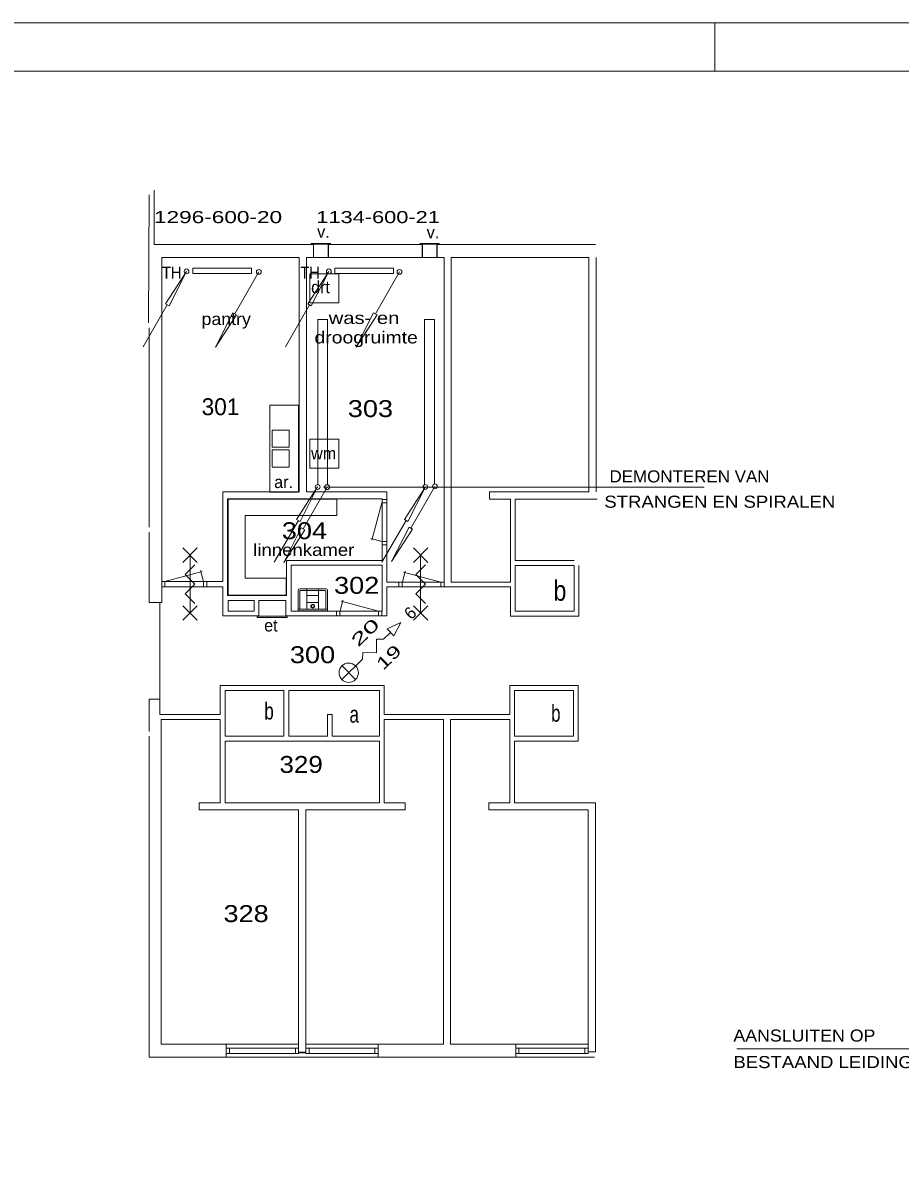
# Model space of a CAD drawing. Extents: x 295824 to 414724, y 24924 to 109024.
# Drawn here: x 358386 to 376562, y 85348 to 109024 of the extents above; entities that cross this region are included whole.
import ezdxf
from ezdxf.enums import TextEntityAlignment as Align

# ---------------------------------------------------------------- set-up
doc = ezdxf.new("R2010")
doc.units = 0
doc.header["$LTSCALE"] = 100
for name, color, linetype, lineweight in [('1', 7, 'Continuous', 13), ('16', 7, 'Continuous', 13), ('61', 7, 'Continuous', 13)]:
    doc.layers.add(name, color=color, linetype=linetype, lineweight=lineweight)

msp = doc.modelspace()

# ---------------------------------------------------------------- linework, layer by layer
at = {"layer": '1'}
msp.add_line((372723.6, 108023.8), (372723.6, 109023.8), dxfattribs=at)
for points in [[(414723.6, 109023.8), (304995.6, 109023.8), (295823.6, 109023.8)], [(304995.6, 25923.8), (413723.6, 25923.8), (413723.6, 108023.8), (304995.6, 108023.8)]]:
    msp.add_lwpolyline(points, dxfattribs=at)
at = {"layer": '16'}
for p, q in [((363274.9, 103866.3), (362774.9, 103000.3)), ((366189.7, 103866.3), (365689.7, 103000.3)), ((360877.9, 102318.1), (361377.9, 103184.1)), ((363826.1, 102318.1), (364326.1, 103184.1)), ((364690.9, 99408.9), (364190.9, 98542.9)), ((364615, 99410.3), (372499.2, 99410.3)), ((366922.9, 99425.5), (366422.9, 98559.5)), ((363593.8, 97854.5), (364093.8, 98720.5)), ((365825.8, 97854.5), (366325.8, 98720.5)), ((383727.1, 87777.8), (373178.7, 87777.8))]:
    msp.add_line(p, q, dxfattribs=at)
for points in [[(361905.5, 103836.3), (363122.2, 103836.3), (363122.2, 103943.5), (361905.5, 103943.5)], [(364850.9, 103836.3), (366067.6, 103836.3), (366067.6, 103943.5), (364850.9, 103943.5)], [(361777.9, 103877.1), (361413.9, 103163.1), (361341.9, 103205.1)], [(364726.1, 103877.1), (364362.1, 103163.1), (364290.1, 103205.1)], [(362374.9, 102307.3), (362738.9, 103021.3), (362810.9, 102979.3)], [(365289.7, 102307.3), (365653.7, 103021.3), (365725.7, 102979.3)], [(364493.8, 99413.5), (364129.8, 98699.5), (364057.8, 98741.5)], [(366725.8, 99413.5), (366361.8, 98699.5), (366289.8, 98741.5)], [(363790.9, 97849.9), (364154.9, 98563.9), (364226.9, 98521.9)], [(366022.9, 97866.5), (366386.9, 98580.5), (366458.9, 98538.5)]]:
    msp.add_lwpolyline(points, close=True, dxfattribs=at)
for points in [[(364494.9, 99450.9), (364494.9, 102882.9), (364697.3, 102882.9), (364697.3, 99462.8)], [(366710, 99450.9), (366710, 102882.9), (366912.5, 102882.9), (366912.5, 99462.8)]]:
    msp.add_lwpolyline(points, dxfattribs=at)
for centre in [(361777.9, 103876.8), (363274.9, 103866.6), (364726.1, 103876.8), (366189.7, 103866.6), (364493.8, 99413.2), (364690.9, 99409.2), (366725.7, 99413.2), (366922.9, 99425.8)]:
    msp.add_circle(centre, 50, dxfattribs=at)
at = {"layer": '61'}
for p, q in [((360992, 102809.9), (361005, 105459.9)), ((361105, 105559.9), (361105, 104434.8)), ((361105, 104434.8), (364405.1, 104434.8)), ((364758.7, 104455), (364360.4, 104455)), ((364360.4, 104455), (364360.4, 104439.9)), ((364758.7, 104439.9), (364360.4, 104439.9)), ((364405.1, 104434.8), (364405.1, 104164.8)), ((364410.7, 104439.9), (364410.7, 104165.5)), ((364709.4, 104439.9), (364709.4, 104165.5)), ((364715.8, 104433.5), (364715.8, 104165)), ((364715.8, 104433.5), (366658.8, 104433.5)), ((364758.7, 104455), (364758.7, 104439.9)), ((367012.4, 104455), (366614.1, 104455)), ((366614.1, 104455), (366614.1, 104439.9)), ((367012.4, 104439.9), (366614.1, 104439.9)), ((366658.8, 104433.5), (366658.8, 104165)), ((366664.4, 104439.9), (366664.4, 104165.5)), ((366963.1, 104439.9), (366963.1, 104165.5)), ((366969.5, 104433.4), (370247.5, 104433.4)), ((366969.5, 104433.4), (366969.5, 104163.4)), ((367012.4, 104455), (367012.4, 104439.9)), ((361262, 97018.8), (361262, 104163.4)), ((364262, 104164.8), (364405.1, 104164.8)), ((364262, 99313.4), (364262, 104163.5)), ((367112, 104163.5), (364262, 104163.5)), ((364709.4, 104165.5), (364410.7, 104165.5)), ((364715.8, 104165), (364861.6, 104165)), ((366512.1, 104165), (366658.8, 104165)), ((366963.1, 104165.5), (366664.4, 104165.5)), ((366969.5, 104163.4), (367112, 104163.4)), ((367112, 97344.7), (367112, 104163.5)), ((370262, 104163.4), (370262, 99313.4)), ((361005, 102709.9), (361005, 98580.1)), ((363552.5, 100587.8), (363902.5, 100587.8)), ((363903.3, 100586.2), (363903.3, 100236.2)), ((363902.5, 100233.7), (363552.5, 100233.7)), ((363552.5, 100179.6), (363902.5, 100179.6)), ((363903.3, 100178), (363903.3, 99828)), ((363902.5, 99825.5), (363552.5, 99825.5)), ((362527.3, 99313.4), (362527.3, 97457.3)), ((364262, 99313.4), (365927.3, 99313.4)), ((362627.3, 97163.1), (362627.3, 99168.1)), ((365825.3, 99083.9), (365618.3, 98311.1)), ((365926.8, 99150.1), (365826, 99150.1)), ((365924.8, 99083.1), (365827.3, 99083.1)), ((365925.2, 99150.1), (365828.5, 99150.1)), ((368587, 97888.4), (368587, 99162.1)), ((370283.5, 99162.1), (368587, 99162.1)), ((365824.7, 98285.5), (365597.9, 98346.2)), ((365924.6, 98283.1), (365826, 98283.1)), ((362000.3, 98152), (361700.3, 97852)), ((361700.3, 98152), (362000.3, 97852)), ((365924.8, 98216.1), (365826, 98216.1)), ((366777.5, 98152), (366477.5, 97852)), ((366477.5, 98152), (366777.5, 97852)), ((361850.3, 96802), (361850.3, 98002)), ((366627.5, 96802), (366627.5, 98002)), ((368587, 97888.4), (369807, 97888.4)), ((369907, 96738.4), (369907, 97788.4)), ((361328.9, 97457.9), (362101.7, 97665)), ((362127.4, 97458.6), (362066.6, 97685.4)), ((366248, 97444.2), (366308.8, 97671.1)), ((367046.5, 97443.6), (366273.7, 97650.6)), ((361329.7, 97343.3), (361329.7, 97457.3)), ((362129.7, 97343.3), (362129.7, 97457.3)), ((362196.7, 97343.3), (362196.7, 97457.3)), ((362527.3, 96743.1), (362527.3, 97343.3)), ((365927.3, 97344.7), (367115.7, 97344.7)), ((365927.3, 97343.1), (365927.3, 96743.1)), ((366178.7, 97344.1), (366178.7, 97443)), ((366245.7, 97344.3), (366245.7, 97443)), ((367045.7, 97344.1), (367045.7, 97443)), ((367112, 97344.7), (368487, 97344.7)), ((367112.7, 97344.7), (367112.7, 97443.1)), ((368487, 96738.4), (368487, 97344.7)), ((363847.3, 97163.1), (362627.3, 97163.1)), ((364087.5, 97269.8), (364087.5, 96854.8)), ((364662.5, 97304.8), (364122.5, 97304.8)), ((364122.5, 96894.8), (364122.5, 97254.8)), ((364137.5, 97269.8), (364647.5, 97269.8)), ((364272.5, 96879.8), (364272.5, 97304.8)), ((364512.5, 97163.1), (364272.5, 97163.1)), ((364512.5, 96879.8), (364512.5, 97304.8)), ((364662.5, 97254.8), (364662.5, 96894.8)), ((364697.5, 96854.8), (364697.5, 97269.8)), ((364956.7, 96843.2), (365017.5, 97070.1)), ((361225, 97018.8), (361225, 94699.2)), ((362000.3, 96952), (361700.3, 96652)), ((361700.3, 96952), (362000.3, 96652)), ((362637.3, 96843.1), (362637.3, 97063.1)), ((363177.3, 97063.1), (362637.3, 97063.1)), ((363177.3, 96843.1), (362637.3, 96843.1)), ((363177.3, 96843.1), (363177.3, 97063.1)), ((363277.3, 96743.1), (363277.3, 97063.1)), ((363837.3, 97063.1), (363277.3, 97063.1)), ((363837.3, 96743.1), (363837.3, 97063.1)), ((364687.5, 96879.8), (364097.5, 96879.8)), ((364097.5, 96844.8), (364687.5, 96844.8)), ((364512.5, 97021.5), (364272.5, 97021.5)), ((364887.4, 96743.1), (364887.4, 96842)), ((364954.4, 96743.3), (364954.4, 96842)), ((365755.2, 96842.6), (364982.4, 97049.6)), ((365754.4, 96743.1), (365754.4, 96842)), ((365821.4, 96743.1), (365821.4, 96842)), ((366777.5, 96952), (366477.5, 96652)), ((366477.5, 96952), (366777.5, 96652)), ((363277.3, 96743.1), (362527.3, 96743.1)), ((363243.1, 96736), (363861.5, 96736)), ((363243.1, 96708.2), (363243.1, 96736)), ((365927.3, 96743.1), (363837.3, 96743.1)), ((369907, 96738.4), (368487, 96738.4)), ((364998.1, 95710.2), (365276, 95422.5)), ((362474.3, 95299.2), (362474.3, 94699.2)), ((365874.3, 95299.2), (362474.3, 95299.2)), ((365874.3, 94699.2), (365874.3, 95299.2)), ((369894.3, 95299.2), (369894.3, 94149.2)), ((362474.3, 94699.2), (361225, 94699.2)), ((361005, 94250.3), (361005, 87604.2)), ((368574.3, 94149.2), (368574.3, 92874.6)), ((368574.3, 94149.2), (369894.3, 94149.2)), ((370249.3, 92874.6), (368574.3, 92874.6)), ((370249.3, 87713.6), (370249.3, 92874.6)), ((361249.3, 87874.2), (364099.3, 87874.2)), ((362600.6, 87599.6), (362600.6, 87869.6)), ((367099.3, 87874.2), (364249.3, 87874.2)), ((365748.6, 87599.6), (365748.6, 87869.7)), ((367249.3, 87874.2), (370099.3, 87874.2)), ((368597.5, 87602.1), (368597.5, 87872.1)), ((361005, 87604.2), (370229.2, 87604.2)), ((362667.3, 87677.8), (362667.3, 87791.7)), ((364032.3, 87677.2), (364032.3, 87791.2)), ((364099.3, 87707.2), (364249.3, 87707.2)), ((364099.3, 87692.2), (364249.3, 87692.2)), ((364315.8, 87678.2), (364315.8, 87792.2)), ((365680.2, 87677.9), (365680.2, 87791.5)), ((368664.2, 87677.8), (368664.2, 87791.7)), ((370029.2, 87677.2), (370029.2, 87791.2)), ((370097.8, 87713.6), (370249.3, 87713.6))]:
    msp.add_line(p, q, dxfattribs=at)
for points in [[(361262, 104163.4), (364112, 104163.4), (364112, 99313.4), (362527.3, 99313.4)], [(363504.2, 99307.9), (364098.9, 99307.9), (364098.9, 101107.9)], [(363504.2, 99307.9), (363504.2, 101107.9), (364098.9, 101107.9)], [(363553.3, 100236.2), (363553.3, 100586.2), (363552.5, 100587.8)], [(363553.3, 99828), (363553.3, 100178), (363552.5, 100179.6)], [(365927.3, 99313.4), (365927.3, 97443.1), (367112.7, 97443.1)], [(362627.3, 99168.1), (365827.3, 99168.1), (365827.3, 97893.1), (363847.3, 97893.1), (363847.3, 97163.1)], [(361005, 98480.1), (361005, 97018.8), (361262, 97018.8)], [(361950.3, 97002), (361750.3, 97202), (361950.3, 97402), (361750.3, 97602), (361950.3, 97802)], [(366727.5, 97002), (366527.5, 97202), (366727.5, 97402), (366527.5, 97602), (366727.5, 97802)], [(361262.7, 97343.3), (361262.7, 97457.3), (362527.3, 97457.3)], [(362527.3, 97343.3), (361262.7, 97343.3), (361262.7, 97457.3)], [(363243.1, 96708.2), (363861.5, 96708.2), (363861.5, 96736)], [(364993.2, 95427.4), (365424.8, 95844.2), (365427.3, 95985.6), (365710.1, 95980.7), (365715, 96263.5), (365856.4, 96261), (366000.2, 96399.9)], [(369894.3, 95299.2), (368474.3, 95299.2), (368474.3, 94699.2)], [(361225, 95018.8), (361005, 95018.8), (361005, 94350.3)], [(364099.3, 87692.2), (364099.3, 92724.2), (362039.3, 92724.2), (362039.3, 92874.2), (362474.3, 92874.2), (362474.3, 94599.2), (361249.3, 94599.2), (361249.3, 87874.2)], [(364249.3, 87692.2), (364249.3, 92724.2), (366309.3, 92724.2), (366309.3, 92874.2), (365874.3, 92874.2), (365874.3, 94599.2), (367099.3, 94599.2), (367099.3, 87874.2)], [(365874.3, 94699.2), (368474.3, 94699.2), (367249.3, 94699.2)], [(370099.3, 87713.6), (370099.3, 92724.2), (368039.3, 92724.2), (368039.3, 92874.2), (368474.3, 92874.2), (368474.3, 94599.2), (367249.3, 94599.2), (367249.3, 87874.2)]]:
    msp.add_lwpolyline(points, dxfattribs=at)
for points in [[(367262, 104163.4), (370112, 104163.4), (370112, 99313.4), (368052, 99313.4), (368052, 99163.4), (368487, 99163.4), (368487, 97438.4), (367262, 97438.4)], [(364333.5, 103228.2), (364333.5, 103828.2), (364933.5, 103828.2), (364933.5, 103228.2)], [(364333.5, 99805.5), (364333.5, 100405.5), (364933.5, 100405.5), (364933.5, 99805.5)], [(362640, 97169.8), (362640, 99163.4), (364890.7, 99163.4), (364890.7, 98823.2), (362990, 98823.2), (362990, 97520.9), (363840.2, 97520.9), (363840.2, 97169.8)], [(363947.3, 97793.1), (365827.3, 97793.1), (365827.3, 96843.1), (363947.3, 96843.1)], [(368587, 97788.4), (369807, 97788.4), (369807, 96838.4), (368587, 96838.4)], [(366069.7, 96328), (365930.8, 96471.9), (366216, 96608.3)], [(362574.3, 94249.2), (363794.3, 94249.2), (363794.3, 95199.2), (362574.3, 95199.2)], [(363894.3, 94249.2), (364694.3, 94249.2), (364694.3, 94699.2), (364794.3, 94699.2), (364794.3, 94249.2), (365774.3, 94249.2), (365774.3, 95199.2), (363894.3, 95199.2)], [(368574.3, 94249.2), (369794.3, 94249.2), (369794.3, 95199.2), (368574.3, 95199.2)], [(362574.3, 92874.2), (365774.3, 92874.2), (365774.3, 94149.2), (362574.3, 94149.2)], [(362600.5, 87677.7), (362600.5, 87791.7), (364099.2, 87791.7), (364099.2, 87677.7)], [(364249.5, 87677.9), (364249.5, 87791.9), (365748.9, 87791.9), (365748.9, 87677.9)], [(368597.4, 87677.7), (368597.4, 87791.7), (370096, 87791.7), (370096, 87677.7)]]:
    msp.add_lwpolyline(points, close=True, dxfattribs=at)
for centre, radius in [((364392.5, 96944.8), 40), ((364392.5, 96944.8), 30), ((365137, 95566.3), 200)]:
    msp.add_circle(centre, radius, dxfattribs=at)
for centre, radius, start, end in [((364122.5, 97269.8), 35, 90, 180), ((364137.5, 97254.8), 15, 90, 180), ((364647.5, 97254.8), 15, 0, 90), ((364662.5, 97269.8), 35, 0, 90), ((364097.5, 96869.8), 10, 90, 180), ((364097.5, 96854.8), 10, 180, 270), ((364137.5, 96894.8), 15, 180, 270), ((364647.5, 96894.8), 15, 270, 0), ((364687.5, 96869.8), 10, 0, 90), ((364687.5, 96854.8), 10, 270, 0)]:
    msp.add_arc(centre, radius, start, end, dxfattribs=at)

# ---------------------------------------------------------------- texts
at = {"layer": '16'}
for s, width, p in [('1296-600-20', 1.4, (361102.5, 104876.5)), ('1134-600-21', 1.35, (364466.3, 104876.5)), ('TH', 0.9, (361270.2, 103727.3)), ('TH', 0.9, (364135.1, 103727.3)), ('DEMONTEREN VAN', 1.05, (370540, 99507.1)), ('STRANGEN EN SPIRALEN', 1.15, (370432.8, 98982.8)), ('AANSLUITEN OP', 1.1, (373107.2, 87927.7)), ('BESTAAND LEIDING NET', 1.15, (373107.2, 87377.7))]:
    msp.add_text(s, height=250, dxfattribs=dict(at, width=width)).set_placement(p)
at = {"layer": '61'}
for s, height, p in [('v.', 250, (364483.7, 104573.4)), ('v.', 250, (366752.9, 104563.3)), ('drt', 250, (364358, 103426.2)), ('301', 350, (362090.2, 100899.9)), ('wm', 250, (364358, 99983.8)), ('ar.', 250, (363592.7, 99390.2)), ('et', 250, (363385.6, 96421.1))]:
    msp.add_text(s, height=height, dxfattribs=at).set_placement(p)
for s, height, width, p in [('pantry', 250, 1.1, (362087.6, 102767.2)), ('was- en', 250, 1.25, (364723.1, 102788.8)), ('droogruimte', 250, 1.2, (364428.2, 102385.5)), ('303', 350, 1.2, (365118.2, 100860.5)), ('304', 350, 1.2, (363751.6, 98332)), ('linnenkamer', 250, 1.15, (363159.1, 97985.7)), ('302', 350, 1.2, (364833.1, 97200.7)), ('300', 350, 1.2, (363918.8, 95764.4)), ('329', 350, 1.15, (363702.5, 93491.8)), ('328', 350, 1.2, (362542.4, 90402.7))]:
    msp.add_text(s, height=height, dxfattribs=dict(at, width=width)).set_placement(p)
for s, height, width, p in [('b', 420, 0.85, (369513.2, 97056.4)), ('b', 350, 0.75, (363486.5, 94597.4)), ('a', 350, 0.75, (365251.3, 94531.5)), ('b', 350, 0.75, (369428.1, 94551.9))]:
    msp.add_text(s, height=height, dxfattribs=dict(at, width=width)).set_placement(p, align=Align.CENTER)
msp.add_text('6', height=250, rotation=44, dxfattribs=at).set_placement((366431.3, 96650.4))
for s, width, p in [('20', 1.75, (365331.4, 96085.6)), ('19', 1.5, (365851.5, 95604.1))]:
    msp.add_text(s, height=250, rotation=44, dxfattribs=dict(at, width=width)).set_placement(p)

doc.saveas('drawing.dxf')
